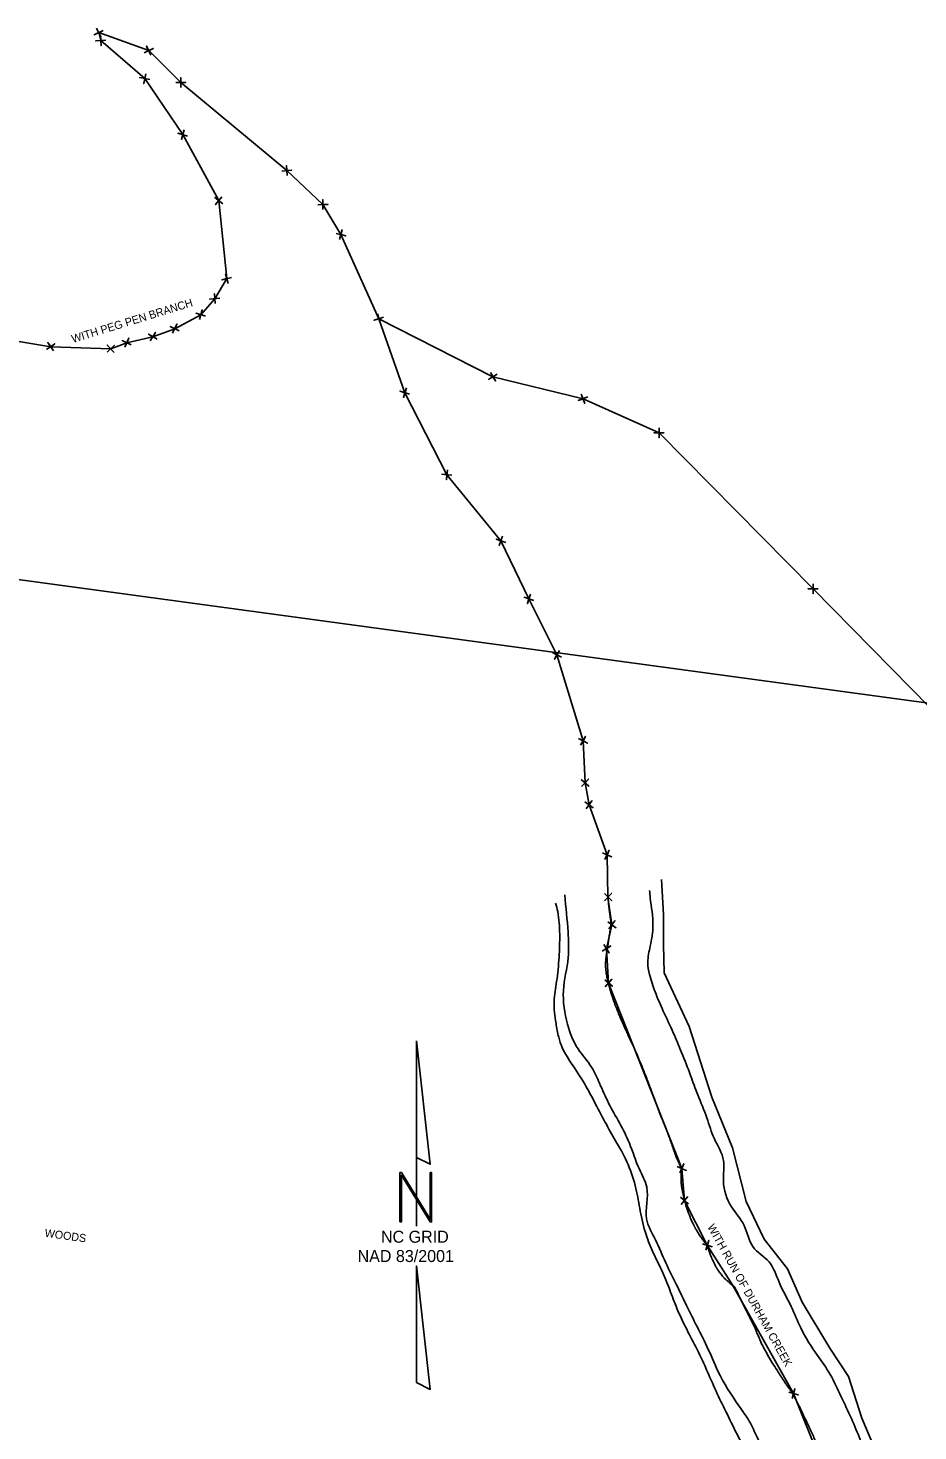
# Model space of a CAD drawing. Extents: x 2627243 to 2636458, y 566398 to 571062.
# Drawn here: x 2634129 to 2634573, y 569301 to 570002 of the extents above; entities that cross this region are included whole.
import ezdxf

# ---------------------------------------------------------------- set-up
doc = ezdxf.new("R2010")
doc.units = 0
for name, color, linetype in [('CTL North Arrow NAD 83 2001 CELL', 7, 'Continuous'), ('Exist Hydro Jurisdictional Stream or Body of Water', 7, 'Continuous'), ('Exist Property Corner CELL', 7, 'Continuous'), ('Exist Property Line', 7, 'Continuous'), ('Exist Property Line Text', 7, 'Continuous'), ('Exist Vegetation Woods Line', 7, 'Continuous'), ('Exist Vegetation Woods Line Text', 7, 'Continuous'), ('Scratch_Level_1', 7, 'Continuous'), ('Scratch_Level_2', 7, 'Continuous')]:
    doc.layers.add(name, color=color, linetype=linetype)

# ---------------------------------------------------------------- blocks, each defined once
blk = doc.blocks.new('CTL NORTH ARROW NAD 83 2001')
at = {"layer": 'CTL North Arrow NAD 83 2001 CELL'}
blk.add_line((0, 0), (0, 0), dxfattribs=at)
for points in [[(-0.003, 1.746), (-0.003, 0.579), (0.135, 0.511)], [(-0.168, -0.065), (-0.154, -0.065), (-0.154, 0.401), (0.135, -0.065), (0.148, -0.065), (0.148, 0.428), (0.135, 0.428), (0.135, -0.038), (-0.154, 0.428), (-0.168, 0.428)], [(-0.003, -1.671), (0.135, -1.739), (-0.003, -0.505)]]:
    blk.add_lwpolyline(points, close=True, dxfattribs=at)
blk.add_lwpolyline([(-0.003, 0.579), (-0.003, -0.107)], dxfattribs=at)
for s, p in [('NC GRID', (-0.358, -0.273)), ('NAD 83/2001', (-0.592, -0.466))]:
    blk.add_text(s, height=0.12, dxfattribs=at).set_placement(p)

msp = doc.modelspace()

# ---------------------------------------------------------------- linework, layer by layer
at = {"layer": 'Exist Hydro Jurisdictional Stream or Body of Water'}
for points in [[(2634396.85, 569568.94), (2634398.53, 569550.39), (2634398.58, 569537.64), (2634396.23, 569521.18), (2634398.28, 569504.33), (2634403.52, 569492.03), (2634410.28, 569482.87), (2634414.25, 569474.82), (2634418.81, 569464.96), (2634429.18, 569444.89), (2634434.17, 569431.88), (2634437.87, 569422.9), (2634437.78, 569407.05), (2634442.18, 569396.54), (2634447.37, 569385.08), (2634452.56, 569374.37), (2634457.16, 569364.96), (2634462.27, 569354.6), (2634467.92, 569343.32), (2634473.41, 569330.96), (2634483.89, 569313.67), (2634489.1, 569305.88), (2634493.02, 569297.93), (2634497.48, 569288.47), (2634501.09, 569279.67), (2634504.67, 569270.14), (2634509.14, 569257.93), (2634512.97, 569247.32), (2634517.16, 569237.03), (2634535.26, 569188.38)], [(2634439.26, 569571.19), (2634439.59, 569567.51), (2634440.97, 569553.79), (2634439.58, 569543.4), (2634438.39, 569535.28), (2634439.25, 569529.24), (2634442.01, 569520.57), (2634446.12, 569510.93), (2634451.13, 569500.07), (2634455.3, 569490.19), (2634459.75, 569478.75), (2634463.32, 569469.08), (2634467.91, 569457.55), (2634471.65, 569447.03), (2634476.22, 569436.22), (2634476.14, 569426), (2634480.26, 569412.99), (2634486.48, 569403.77), (2634490.89, 569393.2), (2634498.99, 569385.5), (2634504, 569375.33), (2634510.06, 569363.23), (2634514.79, 569352.59), (2634523.21, 569338.71), (2634529.54, 569329.23), (2634534.99, 569318.17), (2634540.14, 569307.26), (2634544.47, 569296.7), (2634548.36, 569286.33), (2634552.93, 569273.85), (2634556.48, 569264.02), (2634560.09, 569255.14), (2634586.41, 569214.21)]]:
    msp.add_spline(points, degree=3, dxfattribs=at)
at = {"layer": 'Exist Property Corner CELL'}
for p, q in [((2634164, 570000), (2634164, 570000)), ((2634165, 569996), (2634165, 569996)), ((2634189, 569991), (2634189, 569991)), ((2634187, 569977), (2634187, 569977)), ((2634205, 569975), (2634205, 569975)), ((2634206, 569949), (2634206, 569949)), ((2634258, 569931), (2634258, 569931)), ((2634224, 569916), (2634224, 569916)), ((2634276, 569914), (2634276, 569914)), ((2634285, 569899), (2634285, 569899)), ((2634228, 569877), (2634228, 569877)), ((2634222, 569867), (2634222, 569867)), ((2634215, 569859), (2634215, 569859)), ((2634304, 569857), (2634304, 569857)), ((2634191, 569848), (2634191, 569848)), ((2634202, 569852), (2634202, 569852)), ((2634140, 569843), (2634140, 569843)), ((2634170, 569842), (2634170, 569842)), ((2634178, 569845), (2634178, 569845)), ((2634361, 569828), (2634361, 569828)), ((2634317, 569820), (2634317, 569820)), ((2634406, 569817), (2634406, 569817)), ((2634444, 569800), (2634444, 569800)), ((2634338, 569779), (2634338, 569779)), ((2634365, 569746), (2634365, 569746)), ((2634521, 569722), (2634521, 569722)), ((2634379, 569717), (2634379, 569717)), ((2634393, 569689), (2634393, 569689)), ((2634406, 569646), (2634406, 569646)), ((2634407, 569625), (2634407, 569625)), ((2634409, 569614), (2634409, 569614)), ((2634418, 569589), (2634418, 569589)), ((2634418.47, 569567.87), (2634418.47, 569567.87)), ((2634420.44, 569554.09), (2634420.44, 569554.09)), ((2634417.72, 569542.1), (2634417.72, 569542.1)), ((2634418.81, 569524.94), (2634418.81, 569524.94)), ((2634455.32, 569432.29), (2634455.32, 569432.29)), ((2634456.68, 569416.21), (2634456.68, 569416.21)), ((2634468.13, 569393.86), (2634468.13, 569393.86)), ((2634511.18, 569319.74), (2634511.18, 569319.74))]:
    msp.add_line(p, q, dxfattribs=at)
for points in [[(2634166.26, 570001.06), (2634161.74, 569998.94), (2634164, 570000), (2634165.06, 569997.74), (2634162.94, 570002.26)], [(2634167.49, 569996.18), (2634162.51, 569995.82), (2634165, 569996), (2634165.18, 569993.51), (2634164.82, 569998.49)], [(2634186.74, 569989.94), (2634191.26, 569992.06), (2634189, 569991), (2634187.94, 569993.26), (2634190.06, 569988.74)], [(2634189.46, 569976.53), (2634184.54, 569977.47), (2634187, 569977), (2634186.53, 569974.54), (2634187.47, 569979.46)], [(2634202.5, 569975), (2634207.5, 569975), (2634205, 569975), (2634205, 569977.5), (2634205, 569972.5)], [(2634208.4, 569948.29), (2634203.6, 569949.71), (2634206, 569949), (2634205.29, 569946.6), (2634206.71, 569951.4)], [(2634255.51, 569930.77), (2634260.49, 569931.23), (2634258, 569931), (2634257.77, 569933.49), (2634258.23, 569928.51)], [(2634225.94, 569914.42), (2634222.06, 569917.58), (2634224, 569916), (2634222.42, 569914.06), (2634225.58, 569917.94)], [(2634273.5, 569913.93), (2634278.5, 569914.07), (2634276, 569914), (2634275.93, 569916.5), (2634276.07, 569911.5)], [(2634282.57, 569899.61), (2634287.43, 569898.39), (2634285, 569899), (2634285.61, 569901.43), (2634284.39, 569896.57)], [(2634228.61, 569874.57), (2634227.39, 569879.43), (2634228, 569877), (2634225.57, 569876.39), (2634230.43, 569877.61)], [(2634222.17, 569864.51), (2634221.83, 569869.49), (2634222, 569867), (2634219.51, 569866.83), (2634224.49, 569867.17)], [(2634214.28, 569856.61), (2634215.72, 569861.39), (2634215, 569859), (2634212.61, 569859.72), (2634217.39, 569858.28)], [(2634200.94, 569849.73), (2634203.06, 569854.27), (2634202, 569852), (2634199.73, 569853.06), (2634204.27, 569850.94)], [(2634306.38, 569857.77), (2634301.62, 569856.23), (2634304, 569857), (2634304.77, 569854.62), (2634303.23, 569859.38)], [(2634176.97, 569842.72), (2634179.03, 569847.28), (2634178, 569845), (2634175.72, 569846.03), (2634180.28, 569843.97)], [(2634189.68, 569845.88), (2634192.32, 569850.12), (2634191, 569848), (2634188.88, 569849.32), (2634193.12, 569846.68)], [(2634137.97, 569841.55), (2634142.03, 569844.45), (2634140, 569843), (2634138.55, 569845.03), (2634141.45, 569840.97)], [(2634168.17, 569840.29), (2634171.83, 569843.71), (2634170, 569842), (2634168.29, 569843.83), (2634171.71, 569840.17)], [(2634363.14, 569829.3), (2634358.86, 569826.7), (2634361, 569828), (2634362.3, 569825.86), (2634359.7, 569830.14)], [(2634319.38, 569819.23), (2634314.62, 569820.77), (2634317, 569820), (2634316.23, 569817.62), (2634317.77, 569822.38)], [(2634408.34, 569817.89), (2634403.66, 569816.11), (2634406, 569817), (2634406.89, 569814.66), (2634405.11, 569819.34)], [(2634446.5, 569799.98), (2634441.5, 569800.02), (2634444, 569800), (2634443.98, 569797.5), (2634444.02, 569802.5)], [(2634340.49, 569778.75), (2634335.51, 569779.25), (2634338, 569779), (2634337.75, 569776.51), (2634338.25, 569781.49)], [(2634367.36, 569745.18), (2634362.64, 569746.82), (2634365, 569746), (2634364.18, 569743.64), (2634365.82, 569748.36)], [(2634523.5, 569721.98), (2634518.5, 569722.02), (2634521, 569722), (2634520.98, 569719.5), (2634521.02, 569724.5)], [(2634381.37, 569716.21), (2634376.63, 569717.79), (2634379, 569717), (2634378.21, 569714.63), (2634379.79, 569719.37)], [(2634395.2, 569687.82), (2634390.8, 569690.18), (2634393, 569689), (2634391.82, 569686.8), (2634394.18, 569691.2)], [(2634403.8, 569647.18), (2634408.2, 569644.82), (2634406, 569646), (2634407.18, 569648.2), (2634404.82, 569643.8)], [(2634405.15, 569626.68), (2634408.85, 569623.32), (2634407, 569625), (2634408.68, 569626.85), (2634405.32, 569623.15)], [(2634406.94, 569615.42), (2634411.06, 569612.58), (2634409, 569614), (2634410.42, 569616.06), (2634407.58, 569611.94)], [(2634415.74, 569590.06), (2634420.26, 569587.94), (2634418, 569589), (2634419.06, 569591.26), (2634416.94, 569586.74)], [(2634416.66, 569569.6), (2634420.28, 569566.14), (2634418.47, 569567.87), (2634420.2, 569569.68), (2634416.74, 569566.06)], [(2634418.44, 569555.59), (2634422.44, 569552.59), (2634420.44, 569554.09), (2634421.94, 569556.09), (2634418.94, 569552.09)], [(2634416.38, 569544.22), (2634419.05, 569539.99), (2634417.72, 569542.1), (2634419.83, 569543.44), (2634415.6, 569540.77)], [(2634416.93, 569526.59), (2634420.68, 569523.28), (2634418.81, 569524.94), (2634420.46, 569526.81), (2634417.15, 569523.06)], [(2634453.03, 569433.28), (2634457.61, 569431.29), (2634455.32, 569432.29), (2634456.32, 569434.58), (2634454.32, 569429.99)], [(2634454.77, 569417.82), (2634458.59, 569414.6), (2634456.68, 569416.21), (2634458.3, 569418.12), (2634455.07, 569414.3)], [(2634465.75, 569394.63), (2634470.51, 569393.09), (2634468.13, 569393.86), (2634468.9, 569396.24), (2634467.36, 569391.48)], [(2634508.78, 569320.42), (2634513.59, 569319.06), (2634511.18, 569319.74), (2634511.86, 569322.15), (2634510.51, 569317.34)]]:
    msp.add_lwpolyline(points, dxfattribs=at)
at = {"layer": 'Exist Property Line'}
for p, q in [((2634189, 569991), (2634164, 570000)), ((2634164, 570000), (2634165, 569996)), ((2634165, 569996), (2634187, 569977)), ((2634205, 569975), (2634189, 569991)), ((2634187, 569977), (2634206, 569949)), ((2634258, 569931), (2634205, 569975)), ((2634206, 569949), (2634224, 569916)), ((2634276, 569914), (2634258, 569931)), ((2634224, 569916), (2634228, 569877)), ((2634285, 569899), (2634276, 569914)), ((2634304, 569857), (2634285, 569899)), ((2634228, 569877), (2634222, 569867)), ((2634222, 569867), (2634215, 569859)), ((2634215, 569859), (2634202, 569852)), ((2634317, 569820), (2634304, 569857)), ((2634361, 569828), (2634304, 569857)), ((2634140, 569843), (2634098, 569850)), ((2634191, 569848), (2634178, 569845)), ((2634202, 569852), (2634191, 569848)), ((2634170, 569842), (2634140, 569843)), ((2634178, 569845), (2634170, 569842)), ((2634361, 569828), (2634406, 569817)), ((2634338, 569779), (2634317, 569820)), ((2634406, 569817), (2634444, 569800)), ((2634444, 569800), (2634521, 569722)), ((2634365, 569746), (2634338, 569779)), ((2634379, 569717), (2634365, 569746)), ((2634521, 569722), (2634621, 569620)), ((2634393, 569689), (2634379, 569717)), ((2634406, 569646), (2634393, 569689)), ((2634407, 569625), (2634406, 569646)), ((2634409, 569614), (2634407, 569625)), ((2634418, 569589), (2634409, 569614)), ((2634418.47, 569567.87), (2634418, 569589)), ((2634420.44, 569554.09), (2634418.47, 569567.87)), ((2634417.72, 569542.1), (2634420.44, 569554.09)), ((2634418.81, 569524.94), (2634417.72, 569542.1)), ((2634455.32, 569432.29), (2634418.81, 569524.94)), ((2634456.68, 569416.21), (2634455.32, 569432.29)), ((2634468.13, 569393.86), (2634456.68, 569416.21)), ((2634480.94, 569373.7), (2634468.13, 569393.86)), ((2634511.18, 569319.74), (2634480.94, 569373.7)), ((2634541.16, 569245.62), (2634511.18, 569319.74))]:
    msp.add_line(p, q, dxfattribs=at)
at = {"layer": 'Exist Vegetation Woods Line'}
msp.add_lwpolyline([(2634568.05, 569253.91), (2634545.27, 569307.5), (2634538.61, 569328.27), (2634529.34, 569342.47), (2634515.54, 569365.39), (2634508.13, 569382.05), (2634496.53, 569396.89), (2634487.47, 569415.78), (2634480.76, 569442.5), (2634470.38, 569467.94), (2634459.06, 569503.26), (2634446.62, 569530.01), (2634446.22, 569544.23), (2634446.23, 569559.1), (2634445.21, 569576.65)], dxfattribs=at)
msp.add_spline([(2634392.31, 569564.87), (2634393.36, 569560.61), (2634394.35, 569549.31), (2634394.02, 569537.8), (2634392.82, 569525.73), (2634391.57, 569515.69), (2634392.51, 569504.78), (2634393.84, 569497.81), (2634395.6, 569492.76), (2634400.87, 569483.76), (2634407.47, 569473.34), (2634412.27, 569464.46), (2634417.66, 569454.31), (2634422.98, 569444.93), (2634428.51, 569434.24), (2634432.46, 569422.15), (2634434.6, 569410.97), (2634437.5, 569399.24), (2634441.27, 569389.7), (2634445.91, 569380.1), (2634449.77, 569370.42), (2634453.45, 569361.03), (2634457.81, 569351.87), (2634462.97, 569341.77), (2634468.24, 569330.51), (2634473.09, 569319.6), (2634478, 569309.56), (2634483.7, 569297.95), (2634488.93, 569288.72), (2634494.9, 569280.58), (2634497.98, 569276.36), (2634502.49, 569265.65), (2634505.9, 569255.07), (2634509.62, 569245.29), (2634513.83, 569236.04), (2634518.32, 569226.34), (2634522.84, 569215.63), (2634527.24, 569204.44), (2634530.96, 569194.67), (2634535.09, 569183.92), (2634539.49, 569174.37), (2634545.99, 569164.1), (2634548.89, 569158.54), (2634550.41, 569149.63), (2634549.93, 569147.48), (2634547.91, 569145.79), (2634540.85, 569144.61), (2634527.62, 569145.7), (2634516.13, 569146.64), (2634503.91, 569149.39), (2634493.18, 569152.06), (2634481.31, 569153.59), (2634470.72, 569154.09), (2634458.15, 569156.41), (2634447.07, 569158.65), (2634435.87, 569159.79), (2634423.99, 569160.7), (2634414.05, 569161.8), (2634402.81, 569163.32), (2634392.71, 569164.33), (2634382.43, 569165.64), (2634371.24, 569167.4), (2634360.41, 569169.59), (2634350.14, 569171.52), (2634339.01, 569173.52), (2634328.3, 569175.17), (2634318.02, 569176.48), (2634307.61, 569178.32), (2634296.97, 569180.83), (2634285.8, 569183.22), (2634274.52, 569185.13), (2634263.24, 569187.04), (2634253.16, 569188.67), (2634241.65, 569190.64), (2634229.63, 569192.08), (2634218.43, 569193.21), (2634208.08, 569193.65), (2634195, 569194.83), (2634183.87, 569196.83), (2634172.69, 569198.59), (2634159.53, 569200.55), (2634149.16, 569202), (2634139.17, 569203.49), (2634124.43, 569205.67), (2634114.28, 569206.44), (2634101.37, 569206.7), (2634089.86, 569207.03), (2634085.09, 569207.09)], degree=3, dxfattribs=at)
at = {"layer": 'Scratch_Level_1'}
for points in [[(2634455.29, 569431.95), (2634454.78, 569433.07), (2634454.11, 569434.49), (2634452.98, 569437.1), (2634452.59, 569438.06), (2634452.14, 569439.23), (2634452.07, 569439.43), (2634451.99, 569439.63), (2634451.95, 569439.77), (2634451.91, 569439.85), (2634451.83, 569440.09), (2634451.62, 569440.66), (2634451.42, 569441.22), (2634450.26, 569444.53), (2634449.4, 569447.12), (2634448.48, 569449.57), (2634448.39, 569449.82), (2634448.16, 569450.4), (2634448.05, 569450.7), (2634447.69, 569451.6), (2634447.45, 569452.22), (2634446.69, 569454.1), (2634446.15, 569455.42), (2634445.04, 569458.17), (2634444.47, 569459.6), (2634443.31, 569462.6), (2634442.76, 569464.09), (2634441.73, 569466.89), (2634441.25, 569468.22), (2634440.68, 569469.8), (2634440.56, 569470.11), (2634440.39, 569470.57), (2634440.33, 569470.72), (2634440.22, 569471.02), (2634440.17, 569471.15), (2634439.86, 569471.97), (2634439.61, 569472.63), (2634438.37, 569475.9), (2634437.37, 569478.47), (2634435.35, 569483.52), (2634434.32, 569486.01), (2634433, 569489.1), (2634432.61, 569490.03), (2634432.2, 569490.95), (2634431.93, 569491.56), (2634431.81, 569491.84), (2634431.18, 569493.26), (2634430.63, 569494.45), (2634429.46, 569496.94), (2634428.84, 569498.25), (2634427.56, 569501), (2634426.89, 569502.47), (2634424.97, 569506.81), (2634423.8, 569509.64), (2634422.66, 569512.43), (2634422.64, 569512.47), (2634422.6, 569512.56), (2634422.59, 569512.58), (2634422.52, 569512.77), (2634422.36, 569513.14), (2634422.22, 569513.51), (2634421.93, 569514.25), (2634421.75, 569514.73), (2634421.24, 569516.17), (2634420.93, 569517.09), (2634420.07, 569519.79), (2634419.6, 569521.45), (2634419.13, 569523.19), (2634419.08, 569523.38), (2634418.98, 569523.76), (2634418.93, 569523.92), (2634418.79, 569524.47), (2634418.66, 569524.92), (2634418.26, 569526.53), (2634417.91, 569527.95), (2634417.39, 569531.6), (2634417.21, 569533.86), (2634417.43, 569536.78), (2634417.46, 569537.11), (2634417.51, 569537.53), (2634417.52, 569537.66), (2634417.54, 569537.78), (2634417.55, 569537.87), (2634417.55, 569537.92), (2634417.56, 569537.99), (2634417.6, 569538.26), (2634417.63, 569538.53), (2634417.72, 569539.16), (2634417.77, 569539.58), (2634418.06, 569541.61), (2634418.3, 569543.08), (2634418.6, 569545.08), (2634418.69, 569545.71), (2634418.78, 569546.33), (2634418.79, 569546.37), (2634418.8, 569546.44), (2634418.81, 569546.53), (2634418.84, 569546.75), (2634418.91, 569547.19), (2634418.96, 569547.55), (2634419.07, 569548.24), (2634419.15, 569548.68), (2634419.5, 569550.73), (2634419.73, 569551.97), (2634419.91, 569553.2), (2634419.94, 569553.51), (2634419.96, 569553.8), (2634419.97, 569553.87), (2634419.97, 569553.96), (2634419.97, 569553.93), (2634419.97, 569554.51), (2634419.94, 569555.21), (2634419.74, 569557.13), (2634419.58, 569558.33), (2634419.18, 569561.2), (2634418.95, 569562.87), (2634418.73, 569565.03), (2634418.71, 569565.27), (2634418.67, 569565.64), (2634418.66, 569565.73), (2634418.65, 569565.9), (2634418.61, 569566.35), (2634418.5, 569567.51), (2634418.41, 569568.58), (2634418.34, 569569.3)], [(2634468.08, 569393.61), (2634467.91, 569393.86), (2634467.51, 569394.43), (2634466.22, 569396.15), (2634465.33, 569397.31), (2634463.8, 569399.58), (2634463.25, 569400.43), (2634462.42, 569401.84), (2634462.14, 569402.34), (2634461.79, 569403), (2634461.72, 569403.13), (2634461.58, 569403.4), (2634461.53, 569403.5), (2634461.37, 569403.81), (2634461.27, 569404.01), (2634460.37, 569405.84), (2634459.68, 569407.45), (2634457.85, 569412.22), (2634456.98, 569415.29), (2634456.15, 569418.89), (2634455.99, 569419.6), (2634455.78, 569420.65), (2634455.68, 569421.17), (2634455.56, 569421.77), (2634455.52, 569422.02), (2634455.49, 569422.15), (2634455.49, 569422.16), (2634455.44, 569422.42), (2634455.42, 569422.56), (2634455.05, 569424.8), (2634454.98, 569426.66), (2634455.04, 569429.75), (2634455.17, 569430.99), (2634455.29, 569431.95)], [(2634481.67, 569373.14), (2634480.96, 569373.66), (2634480.06, 569374.33), (2634477.92, 569376.17), (2634476.68, 569377.34), (2634474.76, 569379.63), (2634474.12, 569380.48), (2634473.34, 569381.67), (2634473.18, 569381.91), (2634472.88, 569382.4), (2634472.81, 569382.52), (2634472.55, 569382.96), (2634472.39, 569383.24), (2634471.6, 569384.66), (2634471.1, 569385.72), (2634469.81, 569388.64), (2634469.27, 569390.22), (2634468.47, 569392.55), (2634468.2, 569393.31), (2634468.08, 569393.61)], [(2634568.74, 569202.86), (2634560.2, 569216.14), (2634551.52, 569229.64), (2634542.85, 569243.13), (2634542.58, 569243.55), (2634542.47, 569243.71), (2634541.53, 569245.22), (2634540.99, 569246.2), (2634539.58, 569248.99), (2634538.91, 569250.65), (2634537.88, 569253.46), (2634537.5, 569254.61), (2634537.06, 569255.93), (2634536.94, 569256.3), (2634536.73, 569256.9), (2634536.56, 569257.35), (2634535.02, 569261.61), (2634533.74, 569265.18), (2634531.03, 569272.6), (2634529.69, 569276.27), (2634526.99, 569283.55), (2634525.58, 569287.36), (2634522.98, 569294.06), (2634521.66, 569297.19), (2634518.68, 569303.67), (2634516.89, 569307.34), (2634514.35, 569312.68), (2634513.55, 569314.36), (2634512.39, 569316.7), (2634512.01, 569317.45), (2634511.45, 569318.53), (2634511.26, 569318.89), (2634510.98, 569319.41), (2634511.01, 569319.35), (2634510.93, 569319.48), (2634510.89, 569319.56), (2634510.45, 569320.29), (2634509.63, 569321.46), (2634507.8, 569324.01), (2634507.1, 569324.99), (2634505.95, 569326.71), (2634505.53, 569327.37), (2634505.02, 569328.17), (2634504.76, 569328.57), (2634502.39, 569332.27), (2634500.02, 569335.93), (2634497.08, 569341.16), (2634496.56, 569342.11), (2634495.14, 569344.89), (2634494.56, 569346.18), (2634493.05, 569349.66), (2634492.35, 569351.46), (2634491.54, 569353.31), (2634491.4, 569353.59), (2634490.53, 569355.33), (2634490.1, 569356.2), (2634488.78, 569358.82), (2634487.9, 569360.58), (2634485.23, 569365.9), (2634483.37, 569369.69), (2634481.67, 569373.14)]]:
    msp.add_open_spline(points, degree=3, dxfattribs=at)
at = {"layer": 'Scratch_Level_2'}
msp.add_lwpolyline([(2633945.71, 569750.8), (2635590.54, 569527.29), (2635449.16, 568486.85), (2633804.33, 568710.36)], close=True, dxfattribs=at)

# ---------------------------------------------------------------- block references
at = {"layer": 'CTL North Arrow NAD 83 2001 CELL', "xscale": 50, "yscale": 50}
msp.add_blockref('CTL NORTH ARROW NAD 83 2001', (2634322.94, 569408.77), dxfattribs=at)

# ---------------------------------------------------------------- texts
at = {"layer": 'Exist Property Line Text'}
for s, rotation, p in [('WITH PEG PEN BRANCH', 17.05238, (2634151.12, 569844.85)), ('WITH RUN OF DURHAM CREEK', 299.18273, (2634467.99, 569403.05))]:
    msp.add_text(s, height=4, rotation=rotation, dxfattribs=at).set_placement(p)
at = {"layer": 'Exist Vegetation Woods Line Text'}
msp.add_text('WOODS', height=4, rotation=352.32218, dxfattribs=at).set_placement((2634136.82, 569398.09))

doc.saveas('drawing.dxf')
